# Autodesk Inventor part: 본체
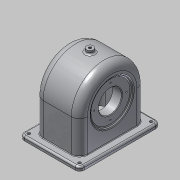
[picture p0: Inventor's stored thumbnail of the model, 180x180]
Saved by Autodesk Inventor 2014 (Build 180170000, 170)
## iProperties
Created: 2016-01
Part Number: 본체
Material: Aluminum 6061
Document SubType Name: Modeling
Designer: user
Mass: 809.565 g
Surface Area: 999.612 cm^2
Volume: 298.733 cm^3
Density: 2.71 g/cm^3
Appearance: Aluminum - Flat
Author: user
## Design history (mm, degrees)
sketch "Sketch4"
  geometry: L1 (-52, 70)-(52, 70); L2 (52, 70)-(52, -70); L3 (52, -70)-(-52, -70); L4 (-52, -70)-(-52, 70); L5 (52, 70)-(-52, -70); 2 further points
  constraints: 10 end point, 2 parallel, 1 coincident, 1 horizontal, 1 midpoint, 1 perpendicular
  dimensions: "d9" = 104 distance of L1.start L1.end; "d10" = 140 distance of L1.end L2.end
extrude "Extrusion3" new body sketch "Sketch4" distance "d11" = 7; taper "d12" = 0 deg
sketch "Sketch5"
  geometry: L1 (-38.5, 57)-(38.5, 57); L2 (38.5, 57)-(38.5, -57); L3 (38.5, -57)-(-38.5, -57); L4 (-38.5, -57)-(-38.5, 57); L5 (38.5, 57)-(-38.5, -57); 2 further points
  constraints: 10 end point, 2 parallel, 1 coincident, 1 horizontal, 1 midpoint, 1 perpendicular
  dimensions: "d13" = 77 distance of L1.start L1.end; "d14" = 114 distance of L3.end L1.start
extrude "Extrusion4" join sketch "Sketch5" distance "d15" = 114; taper "d16" = 0 deg
sketch "Sketch6"
  geometry: L1 (-38.5, 7)-(-38.5, 121) reference; L2 (38.5, 121)-(-38.5, 121) reference; L3 (38.5, 7)-(38.5, 121) reference; L4 (-52, 0)-(52, 0) reference; L5 (0, 0)-(0, 60); L6 (-38.5, 60)-(48.5, 60); L7 (0, 60)-(-38.5, 60); L8 (-38.5, 97.416)-(-35.5, 94.899); L9 (-35.5, 94.899)-(-35.5, 80); L10 (-35.5, 80)-(-19.5, 80); L11 (-19.5, 80)-(-19.5, 88); L12 (-19.5, 88)-(-33.5, 99.747); L13 (-33.5, 99.747)-(-33.5, 111); L14 (-33.5, 111)-(33.5, 111); L15 (33.5, 111)-(33.5, 91); L16 (33.5, 91)-(48.5, 91); L17 (-38.5, 97.416)-(-38.5, 60); L18 (48.5, 91)-(48.5, 60); L19 (52, 7)-(-52, 7) reference
  constraints: 28 end point, 8 perpendicular, 4 parallel, 1 point on line
  dimensions: "d17" = 60 distance of L5.start L5.end; "d19" = 62 diameter of L16 L6; "d22" = 56 diameter of L11.end L6; "d23" = 40 diameter of L10 L6; "d24" = 3 distance between parallel lines of L9 L17; "d25" = 5 distance between parallel lines of L8 L12; "d26" = 16 distance of L9.end L10.end; "d27" = 50 deg angle of L11 L12; "d29" = 5 distance between parallel lines of L1 L13; "d30" = 5 distance between parallel lines of L15 L3; "d31" = 10 distance between parallel lines of L3 L18; "d53" = 102 diameter of L14 L6
revolve "Revolution1" sketch "Sketch6" stored, may be unused: angle "d32" = 90 deg
sketch "Sketch7"
  geometry: C1 r 31 at (53, 57) reference; C2 r 31 at (53, 57); 1 further point
  constraints: 1 centre point, 1 coincident
  dimensions: "d33" = 62 diameter of C2
extrude "Extrusion5" join sketch "Sketch7" distance "d34" = 10; taper "d35" = 0 deg; dims "d45" = 5, "d46" = 0
hole "Hole1" diameter "d38" = 40; stored, may be unused: countersink angle "d42" = 90 deg, drill point angle "d44" = 118 deg; dims "d39" = 6, "d40" = 4, "d41" = 2, "d43" = 8, "d47" = 10, "d48" = 10
sketch "Sketch10"
  geometry: L1 (-33.5, 51)-(33.5, 51); L2 (33.5, 51)-(33.5, -51); L3 (33.5, -51)-(-33.5, -51); L4 (-33.5, -51)-(-33.5, 51); L5 (33.5, 51)-(-33.5, -51); 2 further points
  constraints: 10 end point, 2 parallel, 1 coincident, 1 horizontal, 1 midpoint, 1 perpendicular
  dimensions: "d49" = 102 distance between parallel lines of L1 L3; "d50" = 67 distance of L1.start L1.end
extrude "Extrusion6" cut sketch "Sketch10" distance "d51" = 14; taper "d52" = 0 deg
sketch "Sketch13"
  geometry: 1 further point
sketch "Sketch14"
  geometry: L1 (-22.023, 14)-(-51, 14) reference; L2 (-51, 0)-(-51, 14) reference; L3 (51, 0)-(-51, 0) reference; L4 (51, 0)-(51, 14) reference; L5 (51, 14)-(22.023, 14) reference; L6 (-51, 14)-(-51, 60); L7 (-51, 60)-(-46, 52); L8 (-46, 52)-(-40, 37); L9 (-40, 37)-(-33.75, 27); L10 (-33.75, 27)-(-20, 18); L11 (-20, 18)-(-15.625, 11); L12 (-15.625, 11)-(-3, 11); L13 (-3, 11)-(9, 7); L14 (9, 7)-(22.023, 7); L15 (22.023, 7)-(18.788, 15.087); L16 (18.788, 15.087)-(30.645, 22.498); L17 (30.645, 22.498)-(32.983, 29.512); L18 (32.983, 29.512)-(38.22, 37.512); L19 (38.22, 37.512)-(45.42, 48.512); L20 (45.42, 48.512)-(45.42, 56.512); L21 (51, 14)-(51, 60); L22 (51, 60)-(45.42, 56.512); L23 (-51, 14)-(-51, 0); L24 (51, 0)-(51, 14); L25 (51, 0)-(-51, 0); C1 r 20 at (0, 60) reference; A1 r 51 centre (0, 60) between (22.023, 14) and (-22.023, 14) reference; 1 further point
  constraints: 40 end point, 5 parallel, 5 perpendicular, 4 collinear, 2 point on circle, 2 tangent
extrude "Extrusion8" cut sketch "Sketch14" stored distance "d56" = 67; taper "d57" = 0 deg
sketch "Sketch15"
  geometry: L1 (51, 0)-(51, 60) reference; L2 (-51, 0)-(-51, 60) reference; L3 (51, 0)-(-51, 0) reference; L4 (57, 60)-(57, -6); L5 (57, -6)-(-57, -6); L6 (-57, -6)-(-57, 60); L7 (77, 67)-(77, 148); L8 (77, 148)-(-85.636, 141.817); L9 (-85.636, 141.817)-(-57, 60); L10 (57, 60)-(77, 67); A1 r 51 centre (0, 60) between (51, 60) and (-51, 60) reference; A2 r 57 centre (0, 60) between (57, 60) and (-57, 60); 1 further point
  constraints: 14 end point, 2 point on circle, 1 centre point, 1 parallel, 1 perpendicular, 3 other
  dimensions: "d58" = 6 radial gap between concentric circles of A2 A1
extrude "Extrusion9" cut sketch "Sketch15" stored distance "d59" = 104.75; taper "d60" = 0 deg
workplane "Work Plane3"
  workplane "Work Plane2"
sketch "Sketch16"
  geometry: L1 (38.5, -57)-(38.5, 57) reference; C1 r 6 at (0, 0); 1 further point
  constraints: 1 centre point, 1 coincident
  dimensions: "d62" = 12 diameter of C1
extrude "Extrusion10" join sketch "Sketch16" stored distance "d63" = 104.75; taper "d64" = 0 deg
workplane "Work Plane5"
  workplane "Work Plane4"
sketch "Sketch17"
  geometry: L1 (52, 70)-(-52, 70) reference; L2 (-52, 70)-(-52, -70) reference; L3 (-52, -70)-(52, -70) reference; L4 (52, -70)-(52, 70) reference; L5 (-38.5, 57)-(38.5, 57); L6 (38.5, 57)-(38.5, -57); L7 (38.5, -57)-(-38.5, -57); L8 (-38.5, -57)-(-38.5, 57); L9 (-65, 101)-(66, 101); L10 (66, 101)-(66, -88); L11 (66, -88)-(-65, -88); L12 (-65, -88)-(-65, 101); 1 further point
  constraints: 16 end point, 4 parallel, 2 horizontal, 2 perpendicular
extrude "Extrusion11" cut sketch "Sketch17" distance "d66" = 104.75; taper "d67" = 0 deg
sketch "Sketch18"
  geometry: L1 (52, -70)-(-52, -70); L2 (-52, -70)-(-52, 70); L3 (-52, 70)-(52, 70); L4 (52, 70)-(52, -70); L5 (-52, -70)-(52, 70); L6 (38.5, -57)-(-38.5, -57) reference; L7 (38.5, -57)-(38.5, 57) reference; L8 (-38.5, 57)-(38.5, 57) reference; L9 (-38.5, 57)-(-38.5, -57) reference; 2 further points
  constraints: 10 end point, 2 parallel, 1 coincident, 1 horizontal, 1 midpoint, 1 perpendicular
  dimensions: "d68" = 104 distance of L1.start L1.end; "d69" = 140 distance between parallel lines of L3 L1
extrude "Extrusion12" join sketch "Sketch18" distance "d70" = 7; taper "d71" = 0 deg
sketch "Sketch19"
  geometry: L1 (-38.5, -57)-(38.5, -57) reference; L2 (38.5, -57)-(38.5, 57) reference; L3 (38.5, 57)-(-38.5, 57) reference; L4 (-38.5, 57)-(-38.5, -57) reference; L5 (-33.5, -51)-(-33.5, 51) reference; L6 (-33.5, 51)-(33.5, 51) reference; L7 (33.5, 51)-(33.5, -51) reference; L8 (33.5, -51)-(-33.5, -51) reference; 1 further point
extrude "Extrusion13" join sketch "Sketch19" distance "d72" = 7; taper "d73" = 0 deg
sketch "Sketch20"
  geometry: L1 (-52, 70)-(52, 70); L2 (52, 70)-(52, -70); L3 (52, -70)-(-52, -70); L4 (-52, -70)-(-52, 70); 1 further point
  constraints: 8 end point, 2 parallel, 1 horizontal, 1 perpendicular
extrude "Extrusion14" cut sketch "Sketch20" distance "d74" = 7; taper "d75" = 0 deg
fillet "Fillet1" dims "d76" = 14
fillet "Fillet2" dims "d77" = 9
fillet "Fillet3" dims "d78" = 1
sketch "Sketch21" dims "d79" = 56
  geometry: L1 (0, 0)-(-28, 0); C1 r 34.899 at (0, 0) reference; 2 further points
  constraints: 2 coincident, 2 end point, 1 horizontal, 1 horizontal alignment, 2 other
hole "Hole2" sketch "Sketch21" at (-28, 0) diameter "d80" = 2.459; stored, may be unused: countersink angle "d84" = 90 deg, drill point angle "d86" = 120 deg; dims "d81" = 7, "d82" = 4, "d83" = 2, "d85" = 9
pattern_circular "Circular Pattern1" dims angle "d88" = 360 deg
sketch "Sketch22" dims "d90" = 48
  geometry: L1 (0, 0)-(24, 0); C1 r 31 at (0, 0) reference; 2 further points
  constraints: 2 coincident, 2 end point, 1 horizontal, 1 horizontal alignment, 2 other
hole "Hole3" sketch "Sketch22" at (24, 0) diameter "d91" = 2.459; stored, may be unused: countersink angle "d95" = 90 deg, drill point angle "d97" = 120 deg; dims "d92" = 6, "d93" = 4, "d94" = 2, "d96" = 8
pattern_circular "Circular Pattern2" dims angle "d99" = 360 deg
hole "Hole4" diameter "d103" = 4.459; stored, may be unused: countersink angle "d107" = 90 deg, drill point angle "d109" = 120 deg; dims "d101" = 10, "d102" = 10, "d104" = 12, "d105" = 4, "d106" = 2, "d108" = 8
fillet "Fillet4" dims "d110" = 3
sketch "Sketch23"
  geometry: L1 (-52, -70)-(52, -70) reference; L2 (52, -70)-(52, 70) reference; L3 (52, 70)-(-52, 70) reference; L4 (-52, 70)-(-52, -70) reference; L5 (44, -62)-(-44, -62); L6 (-44, -62)-(-44, 62); L7 (-44, 62)-(44, 62); L8 (44, 62)-(44, -62); 5 further points
  constraints: 8 end point, 4 coincident, 3 other
  dimensions: "d111" = 8 distance between parallel lines of L2 L8
hole "Hole5" sketch "Sketch23" at (-44, 62), (-44, -62), (44, -62), (44, 62) diameter "d112" = 5; stored, may be unused: countersink angle "d116" = 90 deg, drill point angle "d118" = 0 deg; dims "d113" = 12, "d114" = 4, "d115" = 2, "d117" = 8
fillet "Fillet5" dims "d119" = 8
fillet "Fillet6" dims "d120" = 3
fillet "Fillet7" dims "d121" = 3
chamfer "Chamfer1" distance "d122" = 1; stored, may be unused: second distance "d123" = 2, angle "d124" = 45 deg
sketch "Sketch24"
  geometry: L1 (-19.5, 64)-(68.5, 64) reference; L2 (63, 0)-(63, 56) reference; L3 (24.5, 64)-(24.5, 34); 2 further points
  constraints: 2 end point, 1 coincident, 1 midpoint, 1 parallel, 1 other
  dimensions: "d125" = 30 distance of L3.start L3.end; "d126" = 38.5 distance between parallel lines of L3 L2 (derived)
emboss "Emboss1" sketch "Sketch24" dims "d127" = 0.5, "d128" = 0
body "Solid2"
node "Projected Loop3"
other parameters: "d61" = 6, "d65" = -121
